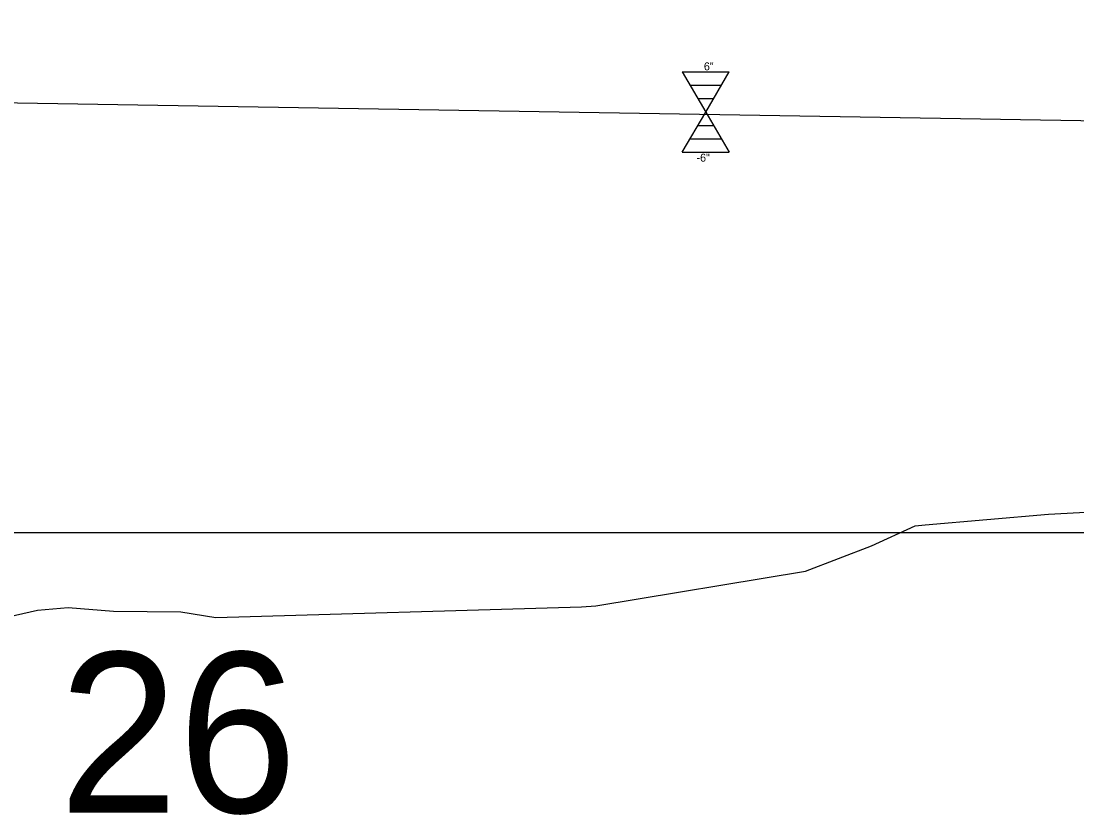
# Model space of a CAD drawing. Extents: x 573468 to 580768, y -57414 to -51768.
# Drawn here: x 575361.5 to 575427.5, y -53423 to -53373.4 of the extents above; entities that cross this region are included whole.
import ezdxf

# ---------------------------------------------------------------- set-up
doc = ezdxf.new("R2010")
doc.units = 0
for name, color, linetype in [('Exist Profile Cell', 7, 'Continuous'), ('Exist Vertical Profile Ground Line', 7, 'Continuous'), ('Exist Vertical Profile Horizontal Axis Label Major', 7, 'Continuous'), ('Pattern 2', 7, 'Continuous'), ('Prop Vertical Profile Grade', 7, 'Continuous')]:
    doc.layers.add(name, color=color, linetype=linetype)

msp = doc.modelspace()

# ---------------------------------------------------------------- linework, layer by layer
at = {"layer": 'Exist Profile Cell'}
msp.add_line((573502.618, -53405.318), (576177.524, -53405.318), dxfattribs=at)
at = {"layer": 'Exist Vertical Profile Ground Line'}
msp.add_lwpolyline([(575359.804, -53410.804), (575362.565, -53410.181), (575364.48, -53410), (575367.315, -53410.231), (575371.533, -53410.272), (575373.706, -53410.636), (575396.551, -53409.973), (575397.445, -53409.91), (575410.54, -53407.744), (575414.655, -53406.161), (575417.386, -53404.915), (575418.009, -53404.858), (575425.714, -53404.174), (575432.688, -53403.803)], dxfattribs=at)
at = {"layer": 'Pattern 2'}
for p, q in [((575402.841, -53376.568), (575405.774, -53376.568)), ((575402.841, -53376.568), (575404.308, -53379.068)), ((575404.308, -53379.068), (575405.774, -53376.568)), ((575403.33, -53377.402), (575405.285, -53377.402)), ((575403.819, -53378.235), (575404.796, -53378.235)), ((575402.841, -53381.568), (575404.308, -53379.068)), ((575404.308, -53379.068), (575405.774, -53381.568)), ((575403.819, -53379.902), (575404.796, -53379.902)), ((575403.33, -53380.735), (575405.285, -53380.735)), ((575402.841, -53381.568), (575405.774, -53381.568))]:
    msp.add_line(p, q, dxfattribs=at)
at = {"layer": 'Prop Vertical Profile Grade'}
msp.add_line((575054.306, -53373.393), (575431.428, -53379.651), dxfattribs=at)

# ---------------------------------------------------------------- texts
at = {"layer": 'Exist Vertical Profile Horizontal Axis Label Major'}
msp.add_text('26', height=10, dxfattribs=at).set_placement((575363.912, -53422.818))
at = {"layer": 'Pattern 2'}
for s, p in [('6"', (575404.195, -53376.467)), ('-6"', (575403.734, -53382.171))]:
    msp.add_text(s, height=0.5, rotation=360, dxfattribs=at).set_placement(p)

doc.saveas('drawing.dxf')
